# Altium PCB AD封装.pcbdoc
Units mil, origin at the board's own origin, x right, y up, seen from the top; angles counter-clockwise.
Board outline 2840 x 1952.6 mil, 4 copper layers (Top Layer, Inner1, Inner2, Bottom Layer); 3 components, 86 nets, 100 pads, 0 vias.
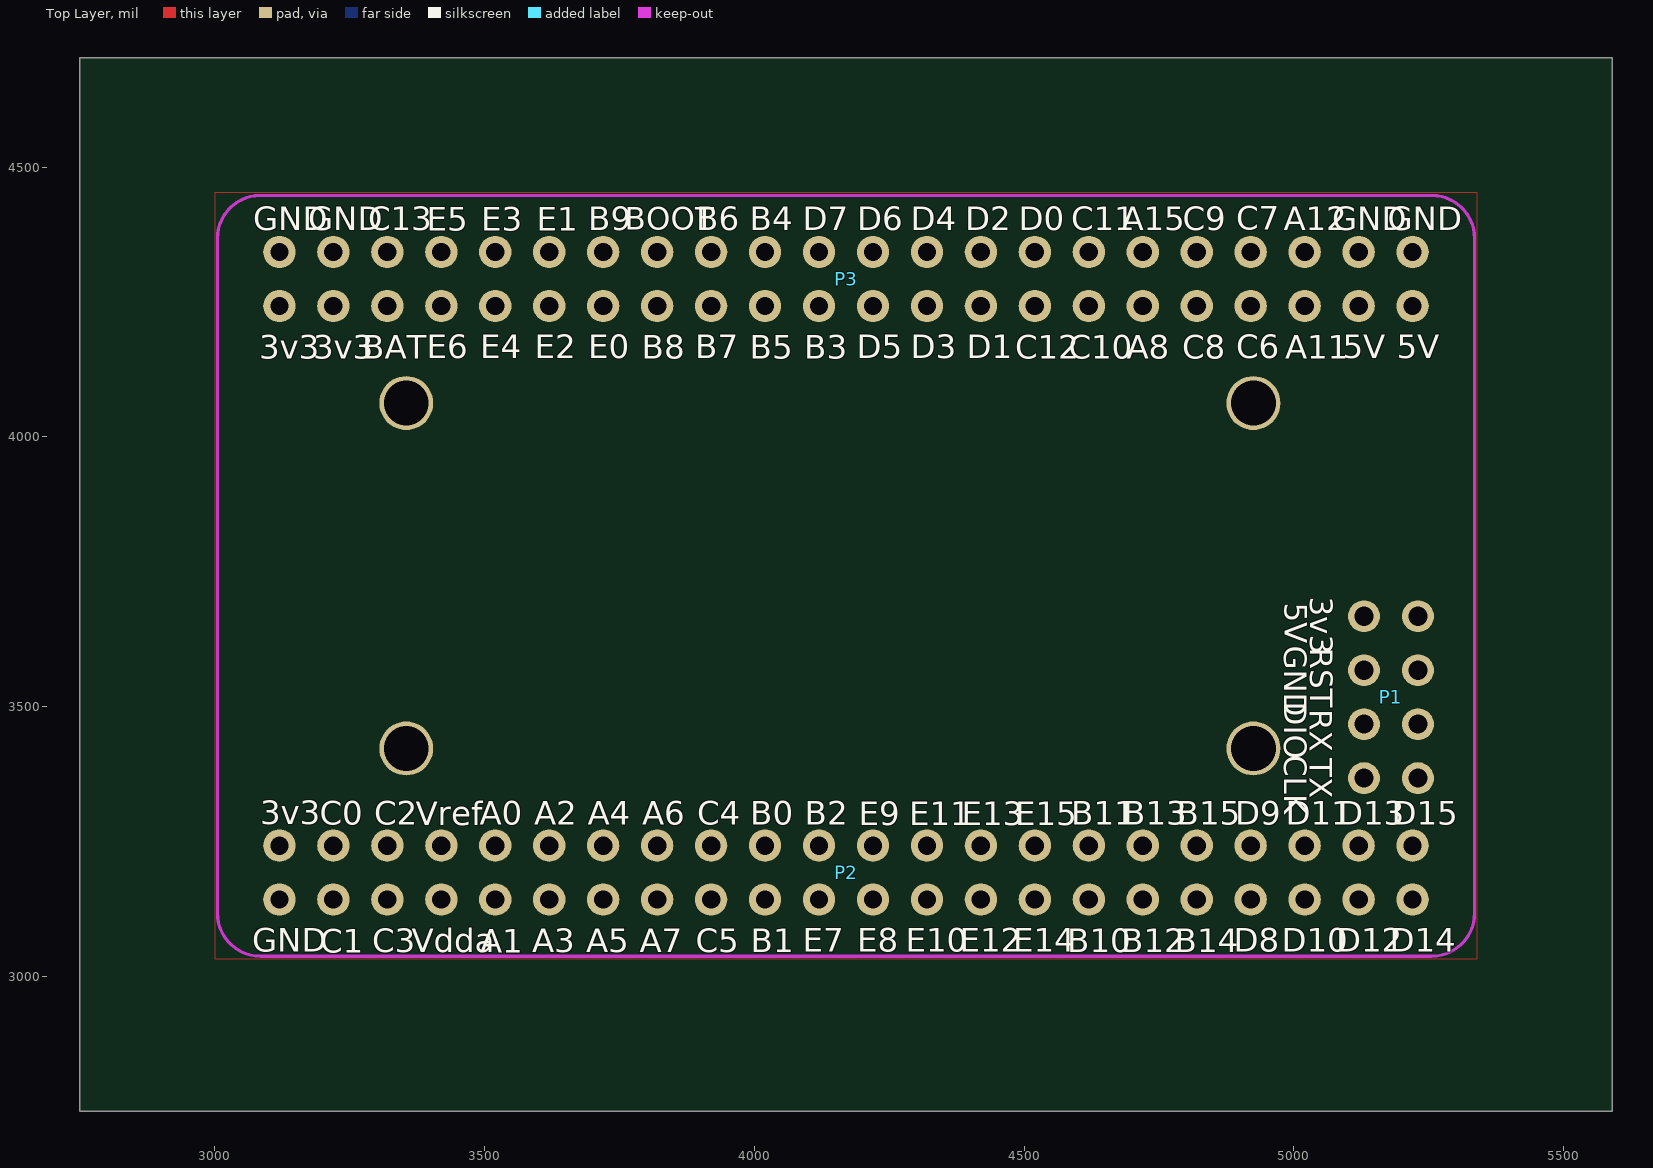
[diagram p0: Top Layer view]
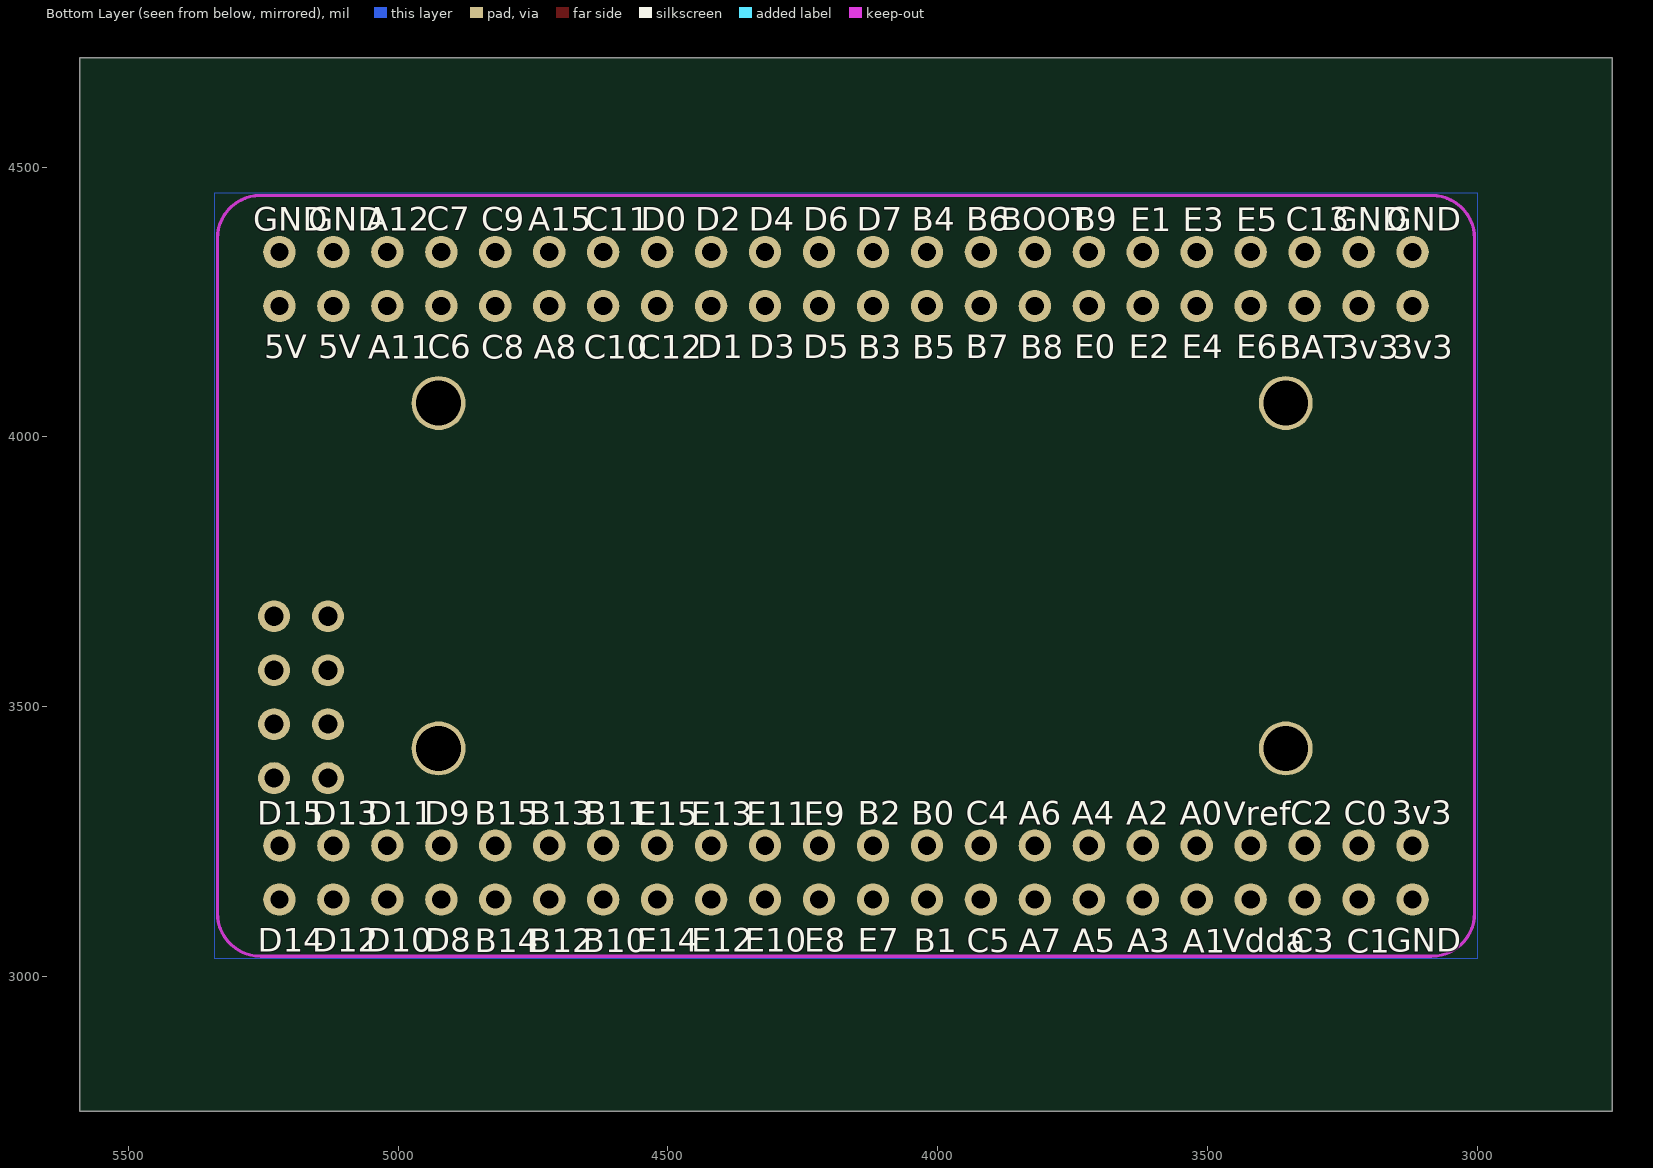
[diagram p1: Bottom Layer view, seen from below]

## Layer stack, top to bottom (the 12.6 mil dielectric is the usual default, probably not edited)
Top Layer: signal copper (thickness not stored)
Dielectric: dielectric 12.6, FR-4, Dk 4.8
Inner1: signal copper (thickness not stored)
Dielectric: dielectric 12.6, FR-4, Dk 4.8
Inner2: signal copper (thickness not stored)
Dielectric: dielectric 12.6, FR-4, Dk 4.8
Bottom Layer: signal copper (thickness not stored)

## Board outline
5590,2750 2750,2750 2750,4702.6 5590,4702.6

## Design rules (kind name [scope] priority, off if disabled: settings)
Clearance copperThickness1oz [All] p1: gap=7 ignorepadtopadclearanceinfootprint=FALSE except(5: SMDPad-SMDPad SMDPad-THPad THPad-THPad SMDPad-Hole THPad-Hole; 6: Track-Track Track-SMDPad Track-THPad Track-Via SMDPad-Via THPad-Via Via-Via Track-Fill SMDPad-Fill THPad-Fill Via-Fill Fill-Fill SMDPad-Region THPad-Region Via-Region Fill-Region Region-Region Track-Poly SMDPad-Poly THPad-Poly Via-Poly Fill-Poly Poly-Poly Track-Text SMDPad-Text THPad-Text Via-Text Fill-Text Region-Text Poly-Text Text-Text Track-Hole Via-Hole Fill-Hole Region-Hole Poly-Hole Text-Hole; 11.8: Track-Region Region-Poly Track-Sheet SMDPad-Sheet THPad-Sheet Via-Sheet Fill-Sheet Region-Sheet Poly-Sheet Text-Sheet Sheet-Hole)
Clearance copperThickness2oz [All] p1: gap=7 ignorepadtopadclearanceinfootprint=FALSE except(6: Track-SMDPad SMDPad-SMDPad Track-THPad SMDPad-THPad THPad-THPad Track-Via SMDPad-Via THPad-Via Via-Via Track-Fill SMDPad-Fill THPad-Fill Via-Fill Fill-Fill SMDPad-Region THPad-Region Via-Region Fill-Region Region-Region Track-Poly SMDPad-Poly THPad-Poly Via-Poly Fill-Poly Poly-Poly Track-Text SMDPad-Text THPad-Text Via-Text Fill-Text Region-Text Poly-Text Text-Text Track-Hole SMDPad-Hole THPad-Hole Via-Hole Fill-Hole Region-Hole Poly-Hole Text-Hole; 8: Track-Track; 11.8: Track-Region Region-Poly Track-Sheet SMDPad-Sheet THPad-Sheet Via-Sheet Fill-Sheet Region-Sheet Poly-Sheet Text-Sheet Sheet-Hole)
DiffPairsRouting differentialPair [All] p1: maxuncoupledlength=10 minlimit=0 maxlimit=6 mostfreqgap=6 toplayer_minwidth=5 toplayer_prefwidth=10 toplayer_maxwidth=100 bottomlayer_minwidth=5 bottomlayer_prefwidth=10 bottomlayer_maxwidth=100 midlayer1_minwidth=5 midlayer1_prefwidth=10 midlayer1_maxwidth=100 midlayer2_minwidth=5 midlayer2_prefwidth=10 midlayer2_maxwidth=100
PasteMaskExpansion pasteMaskExpansion [All] p1: expansion=0
PlaneConnect innerPlane [All] p1: planeconnectstyle=Relief reliefexpansion=20 reliefentries=4 reliefconductorwidth=10 reliefairgap=10
PolygonConnect copperRegion [All] p1: connectstyle=Relief reliefentries=4 reliefconductorwidth=6 polygonreliefangle="90 Angle" airgapwidth=6
RoutingVias viaSize [All] p1: viastyle="Through Hole" holewidth=12 minholewidth=11.8 maxholewidth=248 width=24 minwidth=19.7 maxwidth=393.7
SolderMaskExpansion solderMaskExpansion [All] p1: useseparateexpansions=TRUE expansion=2 expansionbottom=2
Width copperThickness1oz [All] p1: maxlimit=100 minlimit=5 preferedwidth=10
Width copperThickness2oz [All] p1: maxlimit=100 minlimit=8 preferedwidth=10

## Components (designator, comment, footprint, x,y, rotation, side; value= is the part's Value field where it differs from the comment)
P1 "Header-Male-2.54_2x4" "HEADER 2*4" 5230,3367.6 r90 top
P2 "Header 2x22" "header 2x22" 4170,3192.6 r90 top
P3 "Header 2x22" "header 2x22" 4170,4292.6 r90 top

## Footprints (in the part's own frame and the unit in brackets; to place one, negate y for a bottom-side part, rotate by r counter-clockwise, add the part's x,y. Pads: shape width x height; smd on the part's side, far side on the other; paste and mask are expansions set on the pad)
"HEADER 2*4" [mm]
  round 1.5 hole 0.9: 1(0,0) 2(0,2.54) 3(2.54,0) 4(2.54,2.54) 5(5.08,0) 6(5.08,2.54) 7(7.62,0) 8(7.62,2.54)
"header 2x22" [mil]
  round 60 hole 34: 1(-50,1050) 2(50,1050) 3(-50,950) 4(50,950) 5(-50,850) 6(50,850) 7(-50,750) 8(50,750) 9(-50,650) 10(50,650) 11(-50,550) 12(50,550) 13(-50,450) 14(50,450) 15(-50,350) 16(50,350) 17(-50,250) 18(50,250) 19(-50,150) 20(50,150) 21(-50,50) 22(50,50) 23(-50,-50) 24(50,-50) 25(-50,-150) 26(50,-150) 27(-50,-250) 28(50,-250) 29(-50,-350) 30(50,-350) 31(-50,-450) 32(50,-450) 33(-50,-550) 34(50,-550) 35(-50,-650) 36(50,-650) 37(-50,-750) 38(50,-750) 39(-50,-850) 40(50,-850) 41(-50,-950) 42(50,-950) 43(-50,-1050) 44(50,-1050)

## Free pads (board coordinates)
  round 100 hole 83: 1(3355,3422.6) 1(3355,4062.6) 1(4925,3422.6) 1(4925,4062.6)

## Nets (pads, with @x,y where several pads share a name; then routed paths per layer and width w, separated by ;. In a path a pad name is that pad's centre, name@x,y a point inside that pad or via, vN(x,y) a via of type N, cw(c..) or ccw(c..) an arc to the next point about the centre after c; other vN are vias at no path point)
3V3: P1.7 P2.2 P3.1 P3.3
5V: P1.8 P3.41 P3.43
BAT: P3.5
BOOT: P3.16
EXT_ADC_CH1: P2.9
EXT_ADC_CH2: P2.10
EXT_I2C_SCL: P3.18
EXT_I2C_SDA: P3.17
EXT_RX: P3.24
EXT_SPI1_MISO: P3.20
EXT_SPI1_MOSI: P3.19
EXT_SPI1_SCK: P3.21
EXT_SPI2_MISO: P2.16
EXT_SPI2_MOSI: P2.15
EXT_SPI2_SCK: P2.13
EXT_TX: P3.23
FLASH_CLK: P2.34
FLASH_CS: P2.33
FLASH_DI: P2.36
FLASH_DO: P2.35
GND: P1.6 P2.1 P3.2 P3.4 P3.42 P3.44 pad.1
LED1: P2.4
LED2: P2.3
LED3: P2.6
NRST: P1.5
PA2: P2.12
PA3: P2.11
PA4: P2.14
PA8: P3.33
PA9: P1.1
PA10: P1.3
PA11: P3.39
PA12: P3.40
PA13: P1.4
PA14: P1.2
PA15: P3.34
PB0: P2.20
PB1: P2.19
PB2: P2.22
PB8: P3.15
PB9: P3.14
PB10: P2.31
PB11: P2.32
PC3: P2.5
PC4: P2.18
PC5: P2.17
PC6: P3.37
PC7: P3.38
PC8: P3.35
PC9: P3.36
PC10: P3.31
PC11: P3.32
PC12: P3.29
PC13: P3.6
PD0: P3.30
PD1: P3.27
PD2: P3.28
PD3: P3.25
PD4: P3.26
PD7: P3.22
PD8: P2.37
PD9: P2.38
PD10: P2.39
PD11: P2.40
PD12: P2.41
PD13: P2.42
PD14: P2.43
PD15: P2.44
PE0: P3.13
PE1: P3.12
PE2: P3.11
PE3: P3.10
PE4: P3.9
PE5: P3.8
PE6: P3.7
PE7: P2.21
PE8: P2.23
PE9: P2.24
PE10: P2.25
PE11: P2.26
PE12: P2.27
PE13: P2.28
PE14: P2.29
PE15: P2.30
VDDA: P2.7
VREF: P2.8

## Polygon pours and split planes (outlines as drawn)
GND on Bottom Layer (solid, remove dead copper, pour order 2): 3000,3032.6 5340,3032.6 5340,4452.6 3000,4452.6
GND on Top Layer (solid, remove dead copper, pour order 0): 3000,3032.6 5340,3032.6 5340,4452.6 3000,4452.6
GND on Inner1 (solid, remove dead copper): 3000,3032.6 5340,3032.6 5340,4452.6 3000,4452.6
3V3 on Inner2 (solid, remove dead copper): 3000,3032.6 5340,3032.6 5340,4452.6 3000,4452.6

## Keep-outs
Board Outline Layer:
  lines w6: 3005,3117.6 3005,4367.6 cw(c3085,4367.6) 3085,4447.6 5255,4447.6 cw(c5255,4367.6) 5335,4367.6 5335,3117.6 cw(c5255,3117.6) 5255,3037.6 3085,3037.6 cw(c3085,3117.6) 3005,3117.6

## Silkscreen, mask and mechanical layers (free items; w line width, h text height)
Top Silkscreen Layer:
  text "BOOT" at 3759.89,4383.58 h42
  text "C7" at 4893.39,4383.6 h44
  text "GND" at 3071.56,4382.71 h44
  text "GND" at 3173.56,4382.71 h44
  text "C13" at 3284.89,4382.84 h44
  text "B9" at 3692.32,4382.58 h44
  text "B6" at 3892.82,4382.58 h44
  text "B4" at 3991.99,4382.58 h44
  text "D7" at 4089.76,4382.96 h44
  text "D6" at 4190.89,4382.96 h44
  text "D4" at 4290.02,4382.84 h44
  text "D2" at 4390.96,4382.96 h44
  text "D0" at 4490.12,4382.96 h44
  text "C11" at 4587.89,4382.84 h44
  text "A15" at 4680.82,4382.84 h44
  text "C9" at 4794.02,4383.35 h44
  text "A12" at 4981.39,4382.84 h44
  text "GND" at 5071.56,4382.71 h44
  text "GND" at 5173.56,4382.71 h44
  text "E5" at 3393.02,4381.95 h44
  text "E3" at 3493.76,4381.95 h44
  text "E1" at 3596.82,4381.95 h44
  text "E6" at 3392.62,4146 h44
  text "E4" at 3491.75,4146 h44
  text "E2" at 3592.72,4146 h44
  text "E0" at 3691.89,4146 h44
  text "D5" at 4189.55,4146 h44
  text "D3" at 4290.29,4146 h44
  text "D1" at 4393.32,4146 h44
  text "5V" at 5090.72,4145.6 h44
  text "5V" at 5190.72,4145.6 h44
  text "3v3" at 3082.39,4144.87 h44
  text "3v3" at 3182.39,4144.87 h44
  text "BAT" at 3273.09,4144.93 h44
  text "B8" at 3791.75,4145.07 h44
  text "B7" at 3890.82,4145.33 h44
  text "B5" at 3991.49,4145.2 h44
  text "B3" at 4092.22,4144.93 h44
  text "C10" at 4582.95,4144.67 h44
  text "A8" at 4690.15,4145.07 h44
  text "C8" at 4793.42,4145.07 h44
  text "C6" at 4893.62,4145.47 h44
  text "A11" at 4983.75,4144.53 h44
  text "C12" at 4483.82,4144.4 h44
  text "3v3" at 5030.23,3703.6 h42 r270
  text "5V" at 4983,3693.02 h42 r270
  text "GND" at 4982.62,3613.22 h42 r270
  text "RST" at 5030.1,3609.6 h42 r270
  text "DIO" at 4982.49,3509.62 h42 r270
  text "RX" at 5029.51,3495.71 h42 r270
  text "CLK" at 4982.49,3410.02 h42 r270
  text "TX" at 5029.49,3404.87 h42 r270
  text "3v3" at 3084.02,3281.87 h44
  text "C2" at 3295.36,3281.67 h44
  text "A2" at 3592.06,3281.67 h44
  text "C0" at 3194.52,3281.27 h44
  text "A0" at 3491.19,3281.27 h44
  text "A4" at 3691.12,3281.14 h44
  text "A6" at 3791.99,3281.27 h44
  text "C4" at 3894.42,3281.14 h44
  text "B0" at 3992.86,3280.87 h44
  text "B2" at 4093.66,3280.87 h44
  text "B11" at 4586.99,3280.87 h44
  text "B13" at 4683.99,3280.87 h44
  text "B15" at 4783.19,3280.87 h44
  text "D9" at 4891.12,3281.27 h44
  text "D11" at 4985.06,3281.21 h44
  text "D13" at 5082.02,3281.21 h44
  text "D15" at 5181.26,3281.21 h44
  text "Vref" at 3372.79,3280.34 h44
  text "E9" at 4193.76,3280.21 h44
  text "E11" at 4287.66,3280.21 h44
  text "E13" at 4384.62,3280.21 h44
  text "E15" at 4483.86,3280.21 h44
  text "GND" at 3070.03,3045.6 h44
  text "E7" at 4089.83,3045.6 h44
  text "E8" at 4190.77,3045.6 h44
  text "E10" at 4280.3,3045.6 h44
  text "E12" at 4381.13,3045.6 h44
  text "E14" at 4480.2,3045.6 h44
  text "D8" at 4888.17,3045.6 h44
  text "D10" at 4977.7,3045.6 h44
  text "D12" at 5078.57,3045.6 h44
  text "D14" at 5177.63,3045.6 h44
  text "Vdda" at 3365.53,3045.2 h44
  text "A5" at 3688.2,3044.8 h44
  text "A7" at 3787.57,3044.93 h44
  text "C5" at 3891.5,3044.8 h44
  text "B1" at 3993.63,3044.53 h44
  text "B10" at 4579.63,3044.53 h44
  text "B12" at 4680.5,3044.53 h44
  text "B14" at 4779.57,3044.53 h44
  text "C1" at 3195.3,3044 h44
  text "C3" at 3292.23,3044.47 h44
  text "A1" at 3491.97,3044.13 h44
  text "A3" at 3588.97,3044.47 h44
Bottom Silkscreen Layer:
  text "BOOT" at 3883.19,4382.58 h42
  text "C7" at 4946.72,4382.6 h44
  text "GND" at 3167.56,4381.71 h44
  text "GND" at 3267.56,4381.71 h44
  text "C13" at 3355.22,4381.84 h44
  text "B9" at 3747.79,4381.58 h44
  text "B6" at 3947.29,4381.58 h44
  text "B4" at 4048.12,4381.58 h44
  text "D7" at 4150.36,4381.96 h44
  text "D6" at 4249.22,4381.96 h44
  text "D4" at 4350.09,4381.84 h44
  text "D2" at 4449.16,4381.96 h44
  text "D0" at 4549.99,4381.96 h44
  text "C11" at 4652.22,4381.84 h44
  text "A15" at 4759.29,4381.84 h44
  text "C9" at 4846.09,4382.35 h44
  text "A12" at 5058.72,4381.84 h44
  text "GND" at 5166.56,4381.71 h44
  text "GND" at 5268.56,4381.71 h44
  text "E5" at 3447.09,4380.95 h44
  text "E3" at 3546.36,4380.95 h44
  text "E1" at 3643.29,4380.95 h44
  text "E6" at 3446.52,4146 h44
  text "E4" at 3547.39,4146 h44
  text "E2" at 3646.42,4146 h44
  text "E0" at 3747.25,4146 h44
  text "D5" at 4249.59,4146 h44
  text "D3" at 4348.85,4146 h44
  text "D1" at 4445.82,4146 h44
  text "5V" at 5148.42,4145.6 h44
  text "5V" at 5248.42,4145.6 h44
  text "3v3" at 3156.75,4144.87 h44
  text "3v3" at 3256.75,4144.87 h44
  text "BAT" at 3367.05,4144.93 h44
  text "B8" at 3847.39,4145.07 h44
  text "B7" at 3948.32,4145.33 h44
  text "B5" at 4047.65,4145.2 h44
  text "B3" at 4146.92,4144.93 h44
  text "C10" at 4656.19,4144.67 h44
  text "A8" at 4748.99,4145.07 h44
  text "C8" at 4845.72,4145.07 h44
  text "C6" at 4945.52,4145.47 h44
  text "A11" at 5055.39,4144.53 h44
  text "C12" at 4555.32,4144.4 h44
  text "3v3" at 3158.27,3281.87 h44
  text "C2" at 3346.94,3281.67 h44
  text "A2" at 3650.24,3281.67 h44
  text "C0" at 3247.77,3281.27 h44
  text "A0" at 3551.11,3281.27 h44
  text "A4" at 3751.17,3281.14 h44
  text "A6" at 3850.31,3281.27 h44
  text "C4" at 3947.87,3281.14 h44
  text "B0" at 4049.44,3280.87 h44
  text "B2" at 4148.64,3280.87 h44
  text "B11" at 4655.31,3280.87 h44
  text "B13" at 4758.31,3280.87 h44
  text "B15" at 4859.11,3280.87 h44
  text "D9" at 4951.17,3281.27 h44
  text "D11" at 5057.24,3281.21 h44
  text "D13" at 5160.27,3281.21 h44
  text "D15" at 5261.04,3281.21 h44
  text "Vref" at 3469.51,3280.34 h44
  text "E9" at 4248.54,3280.21 h44
  text "E11" at 4354.64,3280.21 h44
  text "E13" at 4457.67,3280.21 h44
  text "E15" at 4558.44,3280.21 h44
  text "GND" at 3167.7,3045.6 h44
  text "E7" at 4147.9,3045.6 h44
  text "E8" at 4246.97,3045.6 h44
  text "E10" at 4357.43,3045.6 h44
  text "E12" at 4456.6,3045.6 h44
  text "E14" at 4557.53,3045.6 h44
  text "D8" at 4949.57,3045.6 h44
  text "D10" at 5060.03,3045.6 h44
  text "D12" at 5159.17,3045.6 h44
  text "D14" at 5260.1,3045.6 h44
  text "Vdda" at 3472.2,3045.2 h44
  text "A5" at 3749.53,3044.8 h44
  text "A7" at 3850.17,3044.93 h44
  text "C5" at 3946.23,3044.8 h44
  text "B1" at 4044.1,3044.53 h44
  text "B10" at 4658.1,3044.53 h44
  text "B12" at 4757.23,3044.53 h44
  text "B14" at 4858.17,3044.53 h44
  text "C1" at 3242.43,3044 h44
  text "C3" at 3345.5,3044.47 h44
  text "A1" at 3545.77,3044.13 h44
  text "A3" at 3648.77,3044.47 h44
